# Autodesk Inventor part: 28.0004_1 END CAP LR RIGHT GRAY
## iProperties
Created: 2007-04
Part Number: 28.0004_1 END CAP LR RIGHT GRAY
Document SubType Name: Modeling
Designer: Andy Moles
Material: ABS Plastic
Mass: 17.1175 g
Surface Area: 77.6421 cm^2
Volume: 16.1486 cm^3
Density: 1.06 g/cm^3
Author: Andy Moles
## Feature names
1. Base1
